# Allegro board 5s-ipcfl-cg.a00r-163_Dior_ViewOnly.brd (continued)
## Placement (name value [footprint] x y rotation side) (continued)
NOREF#46  -  []  13.39 44.26 90 top
NOREF#47  -  []  166 159.41 0 top
NOREF#48  -  []  144.75 74.89 0 top
NOREF#49  -  []  155.12 72.43 0 top
NOREF#50  -  [unnamed#2]  162 -0.25 0 top
NOREF#51  -  []  84.83 83.9 0 top
NOREF#52  -  []  118.2 39.88 0 top
NOREF#53  -  []  45.1 152.23 90 top
NOREF#54  -  []  2.67 129.75 0 top
NOREF#55  -  []  130.87 39.99 0 top
NOREF#56  -  []  106.22 27.09 0 top
NOREF#57  -  []  63.17 20.57 0 top
NOREF#58  -  []  98.11 26.85 0 top
NOREF#59  -  []  86 151.54 90 top
NOREF#60  -  []  129.26 29.83 0 top
NOREF#61  -  []  64.82 19.9 90 top
NOREF#62  -  []  166.02 159.91 0 top
NOREF#63  -  []  137.85 30.01 0 top
NOREF#64  -  []  50.62 160.7 0 top
NOREF#65  -  []  -76.75 -39.55 0 top
NOREF#66  -  []  21.55 47.33 90 top
NOREF#67  -  [unnamed#3]  65.15 137.2 0 top
NOREF#68  -  []  65.18 78.85 0 top
NOREF#69  -  []  137.11 29.24 0 top
NOREF#70  -  []  58.37 67.54 90 top
NOREF#71  -  [unnamed#3]  129.44 12.66 180 bottom
NOREF#72  -  []  9.19 176.57 180 bottom
NOREF#73  -  [unnamed#3]  12.42 157.57 180 bottom
NOREF#74  -  [unnamed#3]  -12.74 171.02 180 bottom
NOREF#75  -  [unnamed#3]  67.16 136.06 180 bottom
NOREF#76  -  [unnamed#3]  3.31 19.25 180 bottom
O2C1  2200PF/50V  [MX_C0402_SMALL_T01]  18.15 90.72 180 bottom
O2C2  100PF/50V  [MX_C0402_SMALL_T01]  154.15 14.42 90 top
O2C6  100PF/50V  [MX_C0402_SMALL_T01]  24.35 83.64 90 top
O2C7  2200PF/50V  [MX_C0402_SMALL_T01]  19.76 90.87 180 bottom
O2C8  100PF/50V  [MX_C0402_SMALL_T01]  16.08 88.74 90 top
O2CB1  0.1UF/16V  [MX_C0402_SMALL_T01]  26.77 98.9 0 bottom
O2CB2  0.1UF/16V  [MX_C0402_SMALL_T01]  12.81 90.91 180 bottom
O2CB3  0.1UF/16V  [MX_C0402_SMALL_T01]  10.65 91.1 180 bottom
O2CB4  0.1UF/16V  [MX_C0402_SMALL_T01]  5.7 94.37 180 bottom
O2CB5  0.1UF/16V  [MX_C0402_SMALL_T01]  18.82 111.81 90 bottom
O2CB6  0.1UF/16V  [MX_C0402_SMALL_T01]  16.53 90.77 0 bottom
O2CB7  1UF/6.3V  [TX_C0201_T009_H14]  24.03 99.58 90 top
O2CB8  0.1UF/16V  [MX_C0402_SMALL_T01]  26.74 105.58 0 bottom
O2CB10  0.1UF/16V  [MX_C0402_SMALL_T01]  26.67 95.93 0 bottom
O2CB11  0.1UF/16V  [MX_C0402_SMALL_T01]  26.71 97.07 180 bottom
O2CB15  0.1UF/16V  [MX_C0402_SMALL_T01]  21.91 90.25 0 bottom
O2CB16  0.1UF/16V  [MX_C0402_SMALL_T01]  5.93 99.06 180 bottom
O2CB17  0.1UF/16V  [MX_C0402_SMALL_T01]  11.23 110.91 90 bottom
O2CB19  0.1UF/16V  [MX_C0402_SMALL_T01]  16.08 90.49 270 top
O2CB20  0.1UF/16V  [MX_C0402_SMALL_T01]  27.51 91.81 0 bottom
O2CB21  0.1UF/16V  [MX_C0402_SMALL_T01]  27.23 112.51 180 bottom
O2Q2  MBT3904DW1T1G  [MX_SOT363_PHILIPS]  9.89 116.71 90 bottom
O2Q3  MBT3904DW1T1G  [MX_SOT363_PHILIPS]  14.18 116.46 270 bottom
O2Q4  MBT3904DW1T1G  [MX_SOT363_PHILIPS]  38.06 110.81 270 bottom
O2Q5  MBT3904DW1T1G  [MX_SOT363_PHILIPS]  44.4 135.6 90 bottom
O2R1  43.2  [MX_R0402_SMALL_T01]  29.82 94.35 270 bottom
O2R9  8.2K  [MX_R0402_SMALL_T01]  11.43 104.3 180 top
O2R10  330K  [MX_R0402_SMALL_T01]  21.74 70.59 0 bottom
O2R12  30KOHM  [MX_R0402_SMALL_T01]  10.45 114.93 180 bottom
O2R13  10.7KOHM  [MX_R0402_SMALL_T01]  14.21 119.33 0 bottom
O2R14  10KOhm  [MX_R0402_SMALL_T01]  13.62 120.75 90 bottom
O2R15  30KOHM  [MX_R0402_SMALL_T01]  14.45 118.34 180 bottom
O2R22  2.74K  [MX_R0402_SMALL_T01]  16.81 92.7 270 top
O2R24  8.2KOHM  [MX_R0402_SMALL_T01]  17.73 92.7 270 top
O2R25  8.2K  [MX_R0402_SMALL_T01]  21.74 71.52 180 bottom
OR3  1K  [MX_R0402_SMALL_T01]  26.08 93.51 180 bottom
OR22  10K  [MX_R0402_SMALL_T01]  18.53 113.45 90 bottom
OR29  10K  [MX_R0402_SMALL_T01]  23.03 113.51 270 bottom
OR34  1K  [MX_R0402_SMALL_T01]  21.94 113.5 270 bottom
OR37  10K  [MX_R0402_SMALL_T01]  13.71 113.36 90 bottom
OR59  10K  [MX_R0402_SMALL_T01]  13.79 98.75 180 top
OR68  10K  [MX_R0402_SMALL_T01]  17.17 114 0 bottom
OR69  10K  [MX_R0402_SMALL_T01]  17.17 113.08 0 bottom
OR70  10K  [MX_R0402_SMALL_T01]  17.17 112.17 0 bottom
OR71  10K  [MX_R0402_SMALL_T01]  17.17 111.25 0 bottom
OR72  10K  [MX_R0402_SMALL_T01]  11.44 103.38 180 top
OR73  10K  [MX_R0402_SMALL_T01]  8.14 110.2 180 bottom
OR74  10K  [MX_R0402_SMALL_T01]  8.14 111.14 180 bottom
OR75  10K  [MX_R0402_SMALL_T01]  8.14 112.05 180 bottom
OR76  10K  [MX_R0402_SMALL_T01]  6.75 117.01 180 bottom
OR77  10K  [MX_R0402_SMALL_T01]  10.45 114.02 0 bottom
OR78  10K  [MX_R0402_SMALL_T01]  10.5 113.1 0 bottom
OR79  10K  [MX_R0402_SMALL_T01]  10.45 112.18 0 bottom
OR109  10K  [MX_R0402_SMALL_T01]  9.37 103.58 180 top
OR111  10K  [MX_R0402_SMALL_T01]  9.37 104.53 180 top
OR112  10K  [MX_R0402_SMALL_T01]  9.37 105.48 180 top
OR118  10K  [MX_R0402_SMALL_T01]  12.88 93.31 180 top
OR119  10K  [MX_R0402_SMALL_T01]  9.37 102.66 180 top
OR120  10K  [MX_R0402_SMALL_T01]  6.05 104.54 180 bottom
OR122  10K  [MX_R0402_SMALL_T01]  6.04 106.37 180 bottom
OR123  10K  [MX_R0402_SMALL_T01]  5.71 107.29 180 bottom
OR124  10K  [MX_R0402_SMALL_T01]  8.02 91.1 0 bottom
OR125  10K  [MX_R0402_SMALL_T01]  6.41 91.1 0 bottom
OR126  10K  [MX_R0402_SMALL_T01]  8.48 93.59 45 top
OR127  10K  [MX_R0402_SMALL_T01]  6.58 92.19 90 top
OR128  10K  [MX_R0402_SMALL_T01]  7.75 103.22 0 top
OR129  10K  [MX_R0402_SMALL_T01]  5.74 101.96 0 top
OR130  10K  [MX_R0402_SMALL_T01]  5.74 101.02 0 top
OR132  10K  [MX_R0402_SMALL_T01]  11.75 112.85 90 bottom
OR133  10K  [MX_R0402_SMALL_T01]  12.69 112.85 90 bottom
OR134  10K  [MX_R0402_SMALL_T01]  14.65 113.36 90 bottom
OR135  10K  [MX_R0402_SMALL_T01]  14.4 110.78 90 bottom
OR136  10K  [MX_R0402_SMALL_T01]  15.6 113.37 90 bottom
OR137  10K  [MX_R0402_SMALL_T01]  15.33 111.31 90 bottom
OR141  10K  [MX_R0402_SMALL_T01]  10.76 96.19 180 top
OR142  10K  [MX_R0402_SMALL_T01]  5.7 96.24 0 bottom
OR143  10K  [MX_R0402_SMALL_T01]  10.75 98.23 0 top
OR144  0Ohm  [MX_R0402_SHORT_SMALL_T01]  9.37 101.74 180 top
OR146  10K  [MX_R0402_SMALL_T01]  18.02 100.78 180 top
OR147  10K  [MX_R0402_SMALL_T01]  18.02 99.84 180 top
OR148  10K  [MX_R0402_SMALL_T01]  16.05 95.06 180 top
OR149  10K  [MX_R0402_SMALL_T01]  16.05 96.05 180 top
OR150  10K  [MX_R0402_SMALL_T01]  16.05 96.97 0 top
OR151  10K  [MX_R0402_SMALL_T01]  16.05 98.01 0 top
OR152  10K  [MX_R0402_SMALL_T01]  36.75 109.03 0 bottom
OR153  10K  [MX_R0402_SMALL_T01]  11.25 92.75 0 top
OR154  1K  [MX_R0402_SMALL_T01]  21.87 74.74 0 bottom
P6  WAFER_HD_1X4P  [MX_WAFER_HD_4P_79_H_F71_LF5]  166.5 59.3 270 top
P12  FPC_CON_12P  [MX_FPC_12P_39_4HOLD_AC]  4.22 123.85 270 top
P70  WAFER_HD_1X4P  [MX_WAF_HD_1X4P_79_H_F71_LF5]  166.69 70.3 270 top
P110  SATA_CON_22P  [MX_SATA_22P_6HD_RA_LOTE_LF5]  42.08 124.48 0 top
P305  TACT_SWITCH_4P  [MX_SW_4P_2HOLD_RA_DIPT]  68.8 7.05 0 top
P466  HEADER_2X7P  [MX_HD_2X7P_100_XINYA_NOMASK]  43.88 50.64 0 bottom
PC1  0.22UF/25V  [TX_C0603]  163.8 153.53 270 top
PC4  1UF/50V  [MX_C0805_SMALL_T02]  164.84 150.43 270 bottom
PC5  0.1UF/25V  [MX_C0402_SMALL_T01]  166.19 140.5 270 top
PC17  1UF/16V  [MX_C0603_SMALL_T01]  47.39 136.72 180 top
PC19  10UF/25V  [MX_C0805_SMALL_T02]  29.5 116.91 270 top
PC20  10UF/25V  [MX_C0805_SMALL_T02]  27.73 116.91 270 top
PC21  0.01UF/50V  [MX_C0402_SMALL_T01]  50.52 138.9 90 top
PC22  2.2UF/6.3V  [MX_C0603_SMALL_T01]  59.99 139.46 0 bottom
PC23  0.1UF/25V  [MX_C0603_SMALL_T01]  57 133.52 90 bottom
PC24  0.01UF/50V  [MX_C0402_SMALL_T01]  51.46 138.9 90 top
PC25  10UF/6.3V  [MX_C0603_SMALL_T01]  81.38 110.48 90 top
PC26  1000PF/50V  [MX_C0402_SMALL_T01]  34.15 117.98 270 top
PC27  22UF/6.3V  [MX_C0603_SMALL_T02]  45.72 119.75 90 top
PC28  39PF/50V  [MX_C0402_SMALL_T01]  81.43 103.8 0 top
PC29  680PF/50V  [MX_C0402_SMALL_T01]  30.33 115.91 180 bottom
PC30  0.047UF/16V  [MX_C0402_SMALL_T01]  81.41 106.11 90 top
PC31  22UF/6.3V  [MX_C0603_SMALL_T02]  81.38 97.88 270 top
PC32  1000PF/50V  [MX_C0402_SMALL_T01]  28.55 115.51 270 bottom
PC33  22UF/6.3V  [MX_C0603_SMALL_T02]  73.79 106.03 180 top
PC34  1000PF/50V  [MX_C0402_SMALL_T01]  32.59 113.72 180 top
PC35  560PF/50V  [MX_C0402_SMALL_T01]  48.94 132.37 90 top
PC36  0.1UF/25V  [MX_C0603_SMALL_T01]  47.47 139.66 90 top
PC37  56PF/50V  [MX_C0402_SMALL_T01]  46.94 134.97 0 top
PC38  22UF/6.3V  [MX_C0603_SMALL_T02]  114.66 113.02 0 top
PC39  22UF/6.3V  [MX_C0603_SMALL_T02]  112.11 111.27 0 bottom
PC40  22UF/6.3V  [MX_C0603_SMALL_T02]  112.11 112.59 0 bottom
PC41  22UF/6.3V  [MX_C0603_SMALL_T02]  112.98 115.31 0 bottom
PC42  22UF/6.3V  [MX_C0603_SMALL_T02]  112.11 109.93 0 bottom
PC43  22UF/6.3V  [MX_C0603_SMALL_T02]  112.95 113.91 0 bottom
PC44  22UF/6.3V  [MX_C0603_SMALL_T02]  114.66 111.62 0 top
PC45  10UF/25V  [MX_C0805_SMALL_T02]  126.74 19.6 180 bottom
PC46  10UF/25V  [MX_C0805_SMALL_T02]  126.74 17.72 180 bottom
PC47  10UF/25V  [MX_C0805_SMALL_T02]  126.74 19.5 180 top
PC48  10UF/25V  [MX_C0805_SMALL_T02]  127.61 15.86 180 bottom
PC49  0.1UF/25V  [MX_C0402_SMALL_T01]  142.34 10.43 0 top
PC50  0.1UF/25V  [MX_C0603_SMALL_T01]  112.81 31.77 90 bottom
PC51  0.1UF/25V  [MX_C0603_SMALL_T01]  107.17 23.75 90 bottom
PC52  330PF/50V  [MX_C0402_SMALL_T01]  132.14 14.93 270 top
PC53  1UF/16V  [MX_C0603_SMALL_T01]  112.1 29.26 90 bottom
PC54  1UF/16V  [MX_C0603_SMALL_T01]  104.12 29.46 90 bottom
PC55  0.1UF/25V  [MX_C0603_SMALL_T01]  99.08 19.19 90 top
PC56  10UF/6.3V  [MX_C0603_SMALL_T01]  100.35 19.19 90 top
PC57  330PF/50V  [MX_C0402_SMALL_T01]  130.66 8.73 180 top
PC58  10PF/50V  [MX_C0402_SMALL_T01]  116.84 18.96 90 top
PC59  1000PF/50V  [MX_C0402_SMALL_T01]  127.53 9.5 0 bottom
PC60  0.1UF/16V  [MX_C0402_SMALL_T01]  112.25 27.17 270 bottom
PC61  56PF/50V  [MX_C0402_SMALL_T01]  104.76 27.47 90 bottom
PC62  0.1UF/16V  [MX_C0402_SMALL_T01]  102.35 26.97 180 bottom
PC63  10UF/25V  [MX_C0805_SMALL_T02]  83.64 28.06 270 bottom
PC64  10UF/25V  [MX_C0805_SMALL_T02]  85.47 28.06 270 bottom
PC65  0.1UF/25V  [MX_C0603_SMALL_T01]  108.57 33.37 270 bottom
PC66  330PF/50V  [MX_C0402_SMALL_T01]  86.13 32.48 90 bottom
PC67  0.1UF/16V  [MX_C0402_SMALL_T01]  103.17 24.63 90 bottom
PC68  330PF/50V  [MX_C0402_SMALL_T01]  86.11 35 90 bottom
PC69  0.1UF/25V  [MX_C0603_SMALL_T01]  63.73 38.9 180 top
PC70  10UF/6.3V  [MX_C0603_SMALL_T01]  63.73 37.68 180 top
PC71  10PF/50V  [MX_C0402_SMALL_T01]  74.7 40.88 0 top
PC72  1000PF/50V  [MX_C0402_SMALL_T01]  84.33 39.66 0 bottom
PC73  0.1UF/16V  [MX_C0402_SMALL_T01]  106.16 33.4 180 bottom
PC74  56PF/50V  [MX_C0402_SMALL_T01]  104.8 31.49 270 bottom
PC75  0.1UF/16V  [MX_C0402_SMALL_T01]  102.6 32 180 bottom
PC76  1UF/6.3V  [TX_C0201_T009_H14]  68.45 43.27 0 bottom
PC78  0.1UF/16V  [MX_C0402_SMALL_T01]  69.95 43.32 270 bottom
PC79  1UF/16V  [MX_C0603_SMALL_T01]  67.38 48.03 0 bottom
PC81  0.1UF/16V  [MX_C0402_SMALL_T01]  69.34 47.87 180 bottom
PC92  10UF/25V  [MX_C0805_SMALL_T02]  76.82 69.85 90 top
PC93  10UF/25V  [MX_C0805_SMALL_T02]  78.6 69.85 90 top
PC94  0.1UF/25V  [MX_C0402_SMALL_T01]  80.48 64.52 180 top
PC95  0.1UF/16V  [MX_C0402_SMALL_T01]  72.63 65.73 270 top
PC96  0.1UF/25V  [MX_C0603_SMALL_T01]  68.92 71.02 0 top
PC97  4.7UF/6.3V  [MX_C0603_SMALL_T01]  69.25 67.66 180 top
PC99  680PF/50V  [MX_C0402_SMALL_T01]  73.01 72.01 0 top
PC102  1000PF/50V  [MX_C0402_SMALL_T01]  74.61 70.69 0 bottom
PC104  56PF/50V  [MX_C0402_SMALL_T01]  74.66 65.53 90 top
PC105  0.1UF/16V  [MX_C0402_SMALL_T01]  76.9 65.33 0 top
PC106  0.1UF/16V  [MX_C0402_SMALL_T01]  73.28 102.48 0 bottom
PC107  22UF/6.3V  [MX_C0603_SMALL_T02]  70.41 99.56 180 bottom
PC108  1UF/25V  [MX_C0603_SMALL_T01]  68.58 102.96 90 bottom
PC109  0.1UF/16V  [MX_C0402_SMALL_T01]  102.59 42.28 270 bottom
PC110  1UF/6.3V  [TX_C0201_T009_H14]  101.62 39.13 0 bottom
PC111  10UF/6.3V  [MX_C0603_SMALL_T01]  101.46 40.76 90 bottom
PC112  10UF/6.3V  [MX_C0603_SMALL_T01]  90.41 39.37 270 bottom
PC113  10UF/6.3V  [MX_C0603_SMALL_T01]  91.68 39.37 270 bottom
PC114  33PF/50V  [MX_C0402_SMALL_T01]  91.8 41.4 90 bottom
PC115  1UF/6.3V  [TX_C0201_T009_H14]  34.8 25.97 90 bottom
PC116  1UF/6.3V  [TX_C0201_T009_H14]  28.75 25.36 90 bottom
PC117  1UF/16V  [MX_C0603_SMALL_T01]  142.41 29.46 0 bottom
PC118  0.1UF/25V  [MX_C0603_SMALL_T01]  140.75 23.31 270 bottom
PC119  0.1UF/25V  [MX_C0402_SMALL_T01]  130.25 20.51 90 bottom
PC120  1000PF/50V  [MX_C0402_SMALL_T01]  136.79 32.41 90 bottom
PC121  10UF/25V  [MX_C0805_SMALL_T02]  136.09 9.59 270 top
PC122  10UF/25V  [MX_C0805_SMALL_T02]  134.31 9.59 270 top
PC123  330PF/50V  [MX_C0402_SMALL_T01]  136.24 12.44 0 bottom
PC124  0.1UF/16V  [MX_C0402_SMALL_T01]  138.03 32 90 bottom
PC125  680PF/50V  [MX_C0402_SMALL_T01]  137.64 14.47 90 bottom
PC126  10UF/6.3V  [MX_C0603_SMALL_T01]  147.13 29.71 180 bottom
PC127  1000PF/50V  [MX_C0402_SMALL_T01]  139.37 17.87 180 bottom
PC128  1UF/6.3V  [TX_C0201_T009_H14]  139.99 32 90 bottom
PC129  330PF/50V  [MX_C0402_SMALL_T01]  135.99 17.06 0 top
PC130  56PF/50V  [MX_C0402_SMALL_T01]  134.58 31.95 0 bottom
PC134  10UF/6.3V  [MX_C0603_SMALL_T01]  133.21 25.02 270 bottom
PC135  10UF/6.3V  [MX_C0603_SMALL_T01]  134.22 27.43 90 bottom
PC760  1UF/6.3V  [MX_C0402_SMALL_T01]  34.52 101.11 270 bottom
PC761  1UF/6.3V  [MX_C0402_SMALL_T01]  35.15 104.74 0 bottom
PC762  0.1UF/16V  [MX_C0402_SMALL_T01]  29.31 106.67 270 bottom
PC802  22UF/6.3V  [MX_C0805_SMALL_T02]  72.52 88.64 0 top
PC803  22UF/6.3V  [MX_C0805_SMALL_T02]  67.9 82.85 180 top
PC804  22UF/6.3V  [MX_C0805_SMALL_T02]  70.99 93.13 270 bottom
PC808  0.01UF/50V  [MX_C0402_SMALL_T01]  70.65 65.73 270 top
PC812  22UF/6.3V  [MX_C0805_SMALL_T02]  72.45 86.74 0 top
PC813  22UF/6.3V  [MX_C0603_SMALL_T02]  72.09 91.97 0 top
PC814  22UF/6.3V  [MX_C0603_SMALL_T02]  72.11 90.54 0 top
PC815  22UF/6.3V  [MX_C0805_SMALL_T02]  72.44 82.92 0 top
PC816  22UF/6.3V  [MX_C0805_SMALL_T02]  72.44 84.83 0 top
PC998  10UF/25V  [MX_C0805_SMALL_T02]  166.39 81.02 0 top
PC999  10UF/25V  [MX_C0805_SMALL_T02]  160.02 145.02 270 top
PC6301  0.1UF/25V  [MX_C0402_SMALL_T01]  36.07 148.48 0 bottom
PC6302  1UF/16V  [MX_C0603_SMALL_T02_H37]  38 140.68 270 bottom
PC6303  10UF/16V  [MX_C0805_SMALL_T02]  39.57 140.4 270 bottom
PC6304  0.1UF/16V  [MX_C0402_SMALL_T01]  35.86 140.81 270 bottom
PC6305  1UF/50V  [MX_C0805_SMALL_T02]  41.83 140.91 180 bottom
PC6306  0.01UF/50V  [MX_C0402_SMALL_T01]  42.44 144.64 90 bottom
PC6307  0.1UF/16V  [MX_C0402_SMALL_T01]  31.24 139.82 90 bottom
PC6308  0.01UF/50V  [MX_C0402_SMALL_T01]  36.8 140.81 270 bottom
PC7310  0.1UF/25V  [MX_C0402_SMALL_T01]  77.32 67.66 270 top
PC7601  10UF/6.3V  [MX_C0603_SMALL_T01]  63.1 61.76 180 bottom
PC7602  10UF/6.3V  [MX_C0603_SMALL_T01]  63.1 60.56 180 bottom
PC7603  33PF/50V  [MX_C0402_SMALL_T01]  65.01 60.65 0 bottom
PC7604  10UF/6.3V  [MX_C0603_SMALL_T01]  62.94 51.4 180 bottom
PC7605  1UF/16V  [MX_C0603_SMALL_T01]  60.73 53.08 90 bottom
PC7606  0.1UF/16V  [MX_C0402_SMALL_T01]  67.94 53.23 0 bottom
PC7607  0.1UF/16V  [MX_C0402_SMALL_T01]  29.54 23.84 270 bottom
PC7801  1UF/6.3V  [TX_C0201_T009_H14]  34.8 24.75 270 bottom
PC7802  1UF/6.3V  [TX_C0201_T009_H14]  29.49 25.36 90 bottom
PC7899  0.1UF/16V  [MX_C0402_SMALL_T01]  35.41 24.37 270 top
PC8498  0.1UF/16V  [MX_C0402_SMALL_T01]  45.19 43.65 0 bottom
PC8499  0.1UF/16V  [MX_C0402_SMALL_T01]  43.74 42.41 270 bottom
PC9001  0.1UF/25V  [TX_C0402]  127.15 152.09 270 bottom
PC9002  0.1UF/25V  [MX_C0402_SMALL_T01]  111.25 152.16 270 top
PC9003  0.1UF/25V  [TX_C0402]  98.83 152.24 270 top
PC9416  0.1UF/16V  [MX_C0402_SMALL_T01]  98.91 8.14 270 top
PC89001  1UF/6.3V  [MX_C0402_SMALL_T01]  86.54 170.47 270 top
PC89002  0.1UF/16V  [MX_C0402_SMALL_T01]  89.08 158.51 0 top
PC89003  2200PF/50V  [MX_C0402_SMALL_T01]  84.56 163.82 180 bottom
PC89004  0.01UF/50V  [MX_C0402_SMALL_T01]  92.96 168.95 90 bottom
PC89005  1000PF/50V  [MX_C0402_SMALL_T01]  89.13 156.96 270 bottom
PC89006  4.7UF/6.3V  [MX_C0603_SMALL_T01]  98.86 168.24 90 top
PC89007  0.047UF/16V  [MX_C0402_SMALL_T01]  86.56 168.39 90 bottom
PC89008  0.1UF/16V  [MX_C0402_SMALL_T01]  88.29 157.6 0 top
PC89009  0.1UF/16V  [MX_C0402_SMALL_T01]  90.75 168.7 180 bottom
PC89010  0.1UF/16V  [MX_C0402_SMALL_T01]  87.35 159.12 270 bottom
PC89011  0.1UF/16V  [MX_C0402_SMALL_T01]  84.94 158.61 180 bottom
PC89012  470PF/50V  [MX_C0402_SMALL_T01]  84.71 166.87 0 bottom
PC89013  47PF/50V  [MX_C0402_SMALL_T01]  85.83 164.33 90 bottom
PC89014  0.1UF/16V  [MX_C0402_SMALL_T01]  86.1 159.45 180 top
PC89015  0.1UF/16V  [MX_C0402_SMALL_T01]  86.51 160.77 270 bottom
PC89016  1000PF/50V  [MX_C0402_SMALL_T01]  85.52 165.95 90 top
PC89017  0.1UF/16V  [MX_C0402_SMALL_T01]  86.82 165.37 270 top
PC89018  560PF/50V  [MX_C0402_SMALL_T01]  85.95 161.91 270 top
PC89019  2200PF/50V  [MX_C0402_SMALL_T01]  85.95 167.25 0 top
PC89020  1000PF/50V  [MX_C0402_SMALL_T01]  84.94 161.91 270 top
PC89021  470PF/50V  [MX_C0402_SMALL_T01]  89.89 165.8 0 top
PC89022  1000PF/50V  [MX_C0402_SMALL_T01]  86.51 162.55 270 bottom
PC89023  470PF/50V  [MX_C0402_SMALL_T01]  98.02 165.22 0 top
PC89024  2200PF/50V  [MX_C0402_SMALL_T01]  100.3 163.44 0 bottom
PC89025  47PF/50V  [MX_C0402_SMALL_T01]  96.8 164.38 90 bottom
PC89026  0.1UF/16V  [MX_C0402_SMALL_T01]  96.09 159.91 270 bottom
PC89027  1000PF/50V  [MX_C0402_SMALL_T01]  98.86 166.49 90 bottom
PC89028  0.1UF/16V  [MX_C0402_SMALL_T01]  97.07 165.85 0 bottom
PC89029  0.1UF/16V  [MX_C0402_SMALL_T01]  98.7 161.91 0 bottom
PC89030  0.1UF/16V  [MX_C0402_SMALL_T01]  97.26 161.53 270 bottom
PC89031  2200PF/50V  [MX_C0402_SMALL_T01]  97.23 166.92 180 bottom
PC89032  120PF/50V  [MX_C0402_SMALL_T01]  94.13 162.35 90 top
PC89033  470PF/50V  [MX_C0402_SMALL_T01]  95.48 165.47 270 top
PC89034  1000PF/50V  [MX_C0402_SMALL_T01]  93.22 162.35 90 top
PC89035  1000PF/50V  [MX_C0402_SMALL_T01]  96.75 161.1 180 top
PC89036  0.1UF/16V  [MX_C0402_SMALL_T01]  87.1 156.96 270 bottom
PC89037  0.1UF/16V  [MX_C0402_SMALL_T01]  95.25 168.9 90 bottom
PC90001  10uF/25V  [TX_C0805_T02_H57]  122.07 151.65 270 bottom
PC90002  4.7UF/25V  [MX_C0805_SMALL_T02_H55]  125.58 150.99 270 bottom
PC90003  10UF/25V  [MX_C0805_SMALL_T02]  130.94 151.75 270 bottom
PC90005  0.1UF/25V  [MX_C0603_SMALL_T01]  119.33 147.11 270 bottom
PC90006  1000PF/50V  [MX_C0402_SMALL_T01]  127.35 155.44 180 top
PC90007  1UF/16V  [TX_C0603_T015_H37]  116.58 150.99 0 bottom
PC90008  680PF/50V  [MX_C0402_SMALL_T01]  122.91 147.16 90 top
PC90009  1000PF/50V  [MX_C0402_SMALL_T01]  129.64 148.45 90 bottom
PC90010  680PF/50V  [MX_C0402_SMALL_T01]  130.17 150.87 90 top
PC90012  10UF/25V  [MX_C0805_SMALL_T02]  103.71 152.92 180 top
PC90013  10uF/25V  [TX_C0805_T02_H57]  103.71 154.75 180 top
PC90016  0.1UF/25V  [MX_C0603_SMALL_T01]  104.01 148.71 270 bottom
PC90017  1000PF/50V  [MX_C0402_SMALL_T01]  109.4 155.56 180 top
PC90018  680PF/50V  [MX_C0402_SMALL_T01]  105.05 147.72 90 top
PC90019  1UF/16V  [TX_C0603_T015_H37]  100.39 152.39 90 bottom
PC90020  1000PF/50V  [MX_C0402_SMALL_T01]  105.46 148.4 90 bottom
PC90021  680PF/50V  [MX_C0402_SMALL_T01]  111.45 150 90 top
PC90100  0.1UF/25V  [TX_C0402]  162.33 150.99 0 top
PC93001  10UF/25V  [MX_C0805_SMALL_T02]  131.82 147.74 270 top
PC93002  10uF/25V  [TX_C0805_T02_H57]  133.6 147.74 270 top
PC93003  10UF/25V  [MX_C0805_SMALL_T02]  134.4 13.73 90 top
PC93005  0.1UF/25V  [MX_C0603_SMALL_T01]  165.61 125.36 90 top
PC93006  1000PF/50V  [MX_C0402_SMALL_T01]  137.87 149.14 270 bottom
PC93007  1UF/25V  [MX_C0603_SMALL_T01]  162.45 121.9 180 top
PC93008  680PF/50V  [MX_C0402_SMALL_T01]  134.69 146.52 180 bottom
PC93009  1000PF/50V  [MX_C0402_SMALL_T01]  131.98 147.11 270 bottom
PC93010  1000PF/50V  [MX_C0402_SMALL_T01]  136.98 142.56 180 top
PC93012  10UF/25V  [MX_C0805_SMALL_T02]  165.45 110.48 180 bottom
PC93013  10UF/25V  [MX_C0805_SMALL_T02]  165.45 108.7 180 bottom
PC93016  0.1UF/25V  [MX_C0603_SMALL_T01]  157.48 119.7 180 bottom
PC93017  1000PF/50V  [MX_C0402_SMALL_T01]  166.91 102.37 180 top
PC93018  1UF/16V  [TX_C0603_T015_H37]  158.94 125.39 0 bottom
PC93019  680PF/50V  [MX_C0402_SMALL_T01]  162.33 108.55 180 top
PC93020  1000PF/50V  [MX_C0402_SMALL_T01]  164.79 97.53 180 top
PC93021  1000PF/50V  [MX_C0402_SMALL_T01]  162.33 102.38 180 top
PC97001  22UF/6.3V  [MX_C0603_SMALL_T02]  126.15 117.53 180 top
PC97002  22UF/6.3V  [MX_C0603_SMALL_T02]  123.1 117.53 0 top
PC97003  22UF/6.3V  [MX_C0603_SMALL_T02]  123.1 116.13 0 top
PC97004  22UF/6.3V  [MX_C0603_SMALL_T02]  118.15 114.9 0 top
PC97005  22UF/6.3V  [MX_C0603_SMALL_T02]  126.15 109.15 180 top
PC97006  22UF/6.3V  [MX_C0603_SMALL_T02]  126.15 111.94 180 top
PC97007  22UF/6.3V  [MX_C0603_SMALL_T02]  126.15 110.55 180 top
PC97008  22UF/6.3V  [MX_C0603_SMALL_T02]  123.1 114.74 0 top
PC97009  22UF/6.3V  [MX_C0603_SMALL_T02]  118.15 110.86 0 top
PC97010  22UF/6.3V  [MX_C0603_SMALL_T02]  123.61 106.48 180 top
PC97011  22UF/6.3V  [MX_C0603_SMALL_T02]  123.1 111.94 0 top
PC97012  22UF/6.3V  [MX_C0603_SMALL_T02]  123.1 110.55 0 top
PC97013  22UF/6.3V  [MX_C0603_SMALL_T02]  115.58 115.96 180 bottom
PC97014  22UF/6.3V  [MX_C0603_SMALL_T02]  123.1 113.34 0 top
PC97015  22UF/6.3V  [MX_C0603_SMALL_T02]  126.15 113.34 180 top
PC97016  22UF/6.3V  [MX_C0603_SMALL_T02]  126.15 114.74 180 top
PC97017  22UF/6.3V  [MX_C0603_SMALL_T02]  123.1 109.15 0 top
PC97018  22UF/6.3V  [MX_C0603_SMALL_T02]  118.15 113.58 0 top
PC97019  22UF/6.3V  [MX_C0603_SMALL_T02]  119.04 106.48 180 top
PC97020  22UF/6.3V  [MX_C0603_SMALL_T02]  118.14 112.23 0 top
PC97021  22UF/6.3V  [MX_C0603_SMALL_T02]  118.15 117.56 0 top
PC97022  22UF/6.3V  [MX_C0603_SMALL_T02]  118.15 116.22 0 top
PC97023  22UF/6.3V  [MX_C0603_SMALL_T02]  126.15 116.13 180 top
PC97024  22UF/6.3V  [MX_C0603_SMALL_T02]  132.68 109.4 270 top
PC97025  22UF/6.3V  [MX_C0603_SMALL_T02]  129.88 114.48 90 top
PC97026  22UF/6.3V  [MX_C0603_SMALL_T02]  128.49 114.48 90 top
PC97027  22UF/6.3V  [MX_C0603_SMALL_T02]  128.49 112.2 270 top
PC97028  22UF/6.3V  [MX_C0603_SMALL_T02]  132.68 114.48 90 top
PC97029  22UF/6.3V  [MX_C0603_SMALL_T02]  128.49 109.4 270 top
PC97030  22UF/6.3V  [MX_C0603_SMALL_T02]  129.88 109.4 270 top
PC97031  22UF/6.3V  [MX_C0603_SMALL_T02]  131.28 114.48 90 top
PC97032  22UF/6.3V  [MX_C0603_SMALL_T02]  131.28 112.2 270 top
PC97033  22UF/6.3V  [MX_C0603_SMALL_T02]  132.68 112.2 270 top
PC97034  22UF/6.3V  [MX_C0603_SMALL_T02]  135.37 112.14 270 bottom
PC97035  22UF/6.3V  [MX_C0603_SMALL_T02]  156.82 116.83 180 bottom
PC97036  22UF/6.3V  [MX_C0603_SMALL_T02]  129.88 112.2 270 top
PC97037  22UF/6.3V  [MX_C0603_SMALL_T02]  132.87 109.21 270 bottom
PC97038  22UF/6.3V  [MX_C0603_SMALL_T02]  157.33 107.94 90 bottom
PC97039  22UF/6.3V  [MX_C0603_SMALL_T02]  136.13 109.22 270 bottom
PC97040  22UF/6.3V  [MX_C0603_SMALL_T02]  134.73 109.22 270 bottom
PC97041  22UF/6.3V  [MX_C0603_SMALL_T02]  132.68 117.1 270 top
PC97042  22UF/6.3V  [MX_C0603_SMALL_T02]  131.28 117.1 270 top
PC97043  22UF/6.3V  [MX_C0603_SMALL_T02]  131.28 109.4 270 top
PC941483  0.1UF/16V  [MX_C0402_SMALL_T01]  133.84 35.18 90 bottom
PC941484  10UF/6.3V  [MX_C0603_SMALL_T01]  137.13 23.94 270 bottom
PC941485  1UF/6.3V  [TX_C0201_T009_H14]  134.42 25.01 270 bottom
PC941488  0.033U/16V  [MX_C0402_SMALL_T01]  134.25 30.4 180 bottom
PC941489  22UF/6.3V  [MX_C0603_SMALL_T02]  129.88 117.1 270 top
PC941490  22UF/6.3V  [MX_C0603_SMALL_T02]  128.49 117.1 270 top
PC941491  22UF/6.3V  [MX_C0603_SMALL_T02]  115.2 114.17 180 bottom
PC941492  22UF/6.3V  [MX_C0603_SMALL_T02]  115.17 112.14 180 bottom
PC941493  22UF/6.3V  [MX_C0603_SMALL_T02]  116.7 109.72 270 bottom
PC941494  22UF/6.3V  [MX_C0603_SMALL_T02]  118.3 109.72 270 bottom
PC941496  0.1UF/25V  [MX_C0402_SMALL_T01]  156.08 162.73 180 top
PC941497  0.01UF/25V  [MX_C0402_SMALL_T01]  167.26 141.34 90 top
PC941502  0.1UF/16V  [MX_C0402_SMALL_T01]  33.37 145.46 270 bottom
PC941579  1000PF/50V  [MX_C0402_SMALL_T01]  70.69 46.09 0 bottom
PC941580  1000PF/50V  [MX_C0402_SMALL_T01]  70.69 45.15 0 bottom
PC941582  1UF/16V  [MX_C0402_SMALL_T01]  65.21 45.43 180 bottom
PC941584  2200PF/50V  [MX_C0402_SMALL_T01]  163.68 48.88 270 bottom
PC941585  2200PF/50V  [MX_C0402_SMALL_T01]  168.15 48.83 270 bottom
PC941586  680PF/50V  [MX_C0402_SMALL_T01]  92.58 147.28 180 top
PC941587  10UF/25V  [MX_C0805_SMALL_T02]  90.42 153.18 270 top
PC941588  0.1UF/25V  [MX_C0603_SMALL_T01]  87.2 145.99 180 top
PC941589  680PF/50V  [MX_C0402_SMALL_T01]  98.82 150.6 90 top
PC941590  1UF/16V  [TX_C0603_T015_H37]  90.07 141.34 90 top
PC941591  1000PF/50V  [MX_C0402_SMALL_T01]  96.82 156.05 180 bottom
PC941601  10UF/25V  [MX_C0805_SMALL_T02]  137.92 9.51 270 top
PC941602  1UF/6.3V  [TX_C0201_T009_H14]  42.44 41.06 180 bottom
PC941603  0.1UF/16V  [MX_C0402_SMALL_T01]  40.99 45.71 0 bottom
PC941604  1000PF/50V  [MX_C0402_SMALL_T01]  38.2 40.81 180 bottom
PC941605  1UF/16V  [MX_C0402_SMALL_T01]  45.53 42.35 0 bottom
PC941608  0.1UF/16V  [MX_C0402_SMALL_T01]  40.28 40.78 0 bottom
PC941609  1000PF/50V  [MX_C0402_SMALL_T01]  38.2 41.72 180 bottom
PC941610  1UF/16V  [MX_C0603_SMALL_T01]  43.64 45.82 180 bottom
PC941611  1UF/16V  [MX_C0603_SMALL_T01]  98.86 8.5 270 bottom
PC941612  0.1UF/16V  [MX_C0402_SMALL_T01]  95.6 13.66 90 bottom
PC941613  1000PF/50V  [MX_C0402_SMALL_T01]  94.21 8.88 270 top
PC941614  1UF/16V  [MX_C0402_SMALL_T01]  99.9 10.63 0 bottom
PC941617  0.1UF/16V  [MX_C0402_SMALL_T01]  94.56 8.17 270 bottom
PC941618  1UF/16V  [MX_C0603_SMALL_T01]  97.2 13.44 180 bottom
PC941619  1000PF/50V  [MX_C0402_SMALL_T01]  94.08 11.17 180 bottom
PC941620  0.1UF/50V  [MX_C0603_SMALL_T01]  155.85 161.46 180 top
PC941622  10UF/25V  [MX_C0805_SMALL_T02]  129.13 152.26 270 bottom
PC941623  1000PF/50V  [MX_C0402_SMALL_T01]  90.52 148.71 90 bottom
PC941626  10uF/25V  [TX_C0805_T02_H57]  92.2 153.18 270 top
PC941663  22UF/6.3V  [MX_C0603_SMALL_T02]  124.46 114.32 0 bottom
PC941664  22UF/6.3V  [MX_C0603_SMALL_T02]  124.46 115.84 0 bottom
PC941665  22UF/6.3V  [MX_C0603_SMALL_T02]  124.46 117.34 0 bottom
PC941666  0.01UF/25V  [MX_C0402_SMALL_T01]  167.26 139.66 270 top
PC941667  1UF/6.3V  [TX_C0201_T009_H14]  68.45 42.56 0 bottom
PC941669  1UF/6.3V  [TX_C0201_T009_H14]  101.62 38.39 0 bottom
PC941670  1UF/6.3V  [TX_C0201_T009_H14]  135.2 25.01 270 bottom
PC941671  1UF/6.3V  [TX_C0201_T009_H14]  44.5 41.14 90 bottom
PCE2  220UF/6.3V  [MX_CESMD_260X260_COLAY]  76.98 100.47 0 top
PCE3  560UF/2.5V  [MX_CESMD_260X260_SAN]  50.02 116.57 270 top
PCE4  560UF/2.5V  [MX_CESMD_260X260_SAN]  57.41 116.57 270 top
PCE5  220UF/6.3V  [MX_CESMD_260X260_COLAY]  106.78 16.75 180 top
PCE6  220UF/6.3V  [MX_CESMD_260X260_COLAY]  97.13 14.09 90 top
PCE7  220UF/6.3V  [MX_CESMD_260X260_COLAY]  66.17 33.39 90 top
PCE9  820UF/2.5V  [MX_CE_98_BD268_H374_37_LFH]  149.53 16.68 0 top
PCE31  27uF/25V  [MX_CESMD_209X209_CHEMICON]  145.49 154.02 0 top
PCE125  27uF/25V  [MX_CESMD_209X209_CHEMICON]  136.1 153.76 0 top
PCE690  220UF/6.3V  [MX_CESMD_260X260_COLAY]  67.38 44.08 0 top
PCE97027  560uF/2.5V  [MX_CE_79_BD217_H354HD31_LF5]  102.13 140.81 0 top
PCE97028  560uF/2.5V  [MX_CE_79_BD217_H354HD31_LF5]  140.18 140.68 270 top
PCE97030  560UF/2.5V  [MX_CESMD_260X260_SAN]  117.55 142.31 270 top
PCE97031  560uF/2.5V  [MX_CE_79_BD217_H354HD31_LF5]  133.68 140.71 0 top
PCE97032  330UF/2V  [MX_C7343D_H83]  131.21 115.37 90 bottom
PCE97033  560uF/2.5V  [MX_CE_79_BD217_H354HD31_LF5]  166.67 120.67 270 top
PCE97034  560uF/2.5V  [MX_CE_79_BD217_H354HD31_LF5]  162.66 141.16 270 top
PCE97035  560uF/2.5V  [MX_CE_79_BD217_H354HD31_LF5]  151.42 141.16 270 top
PCE97037  560uF/2.5V  [MX_CE_79_BD217_H354HD31_LF5]  145.85 140.81 270 top
PCE97038  560uF/2.5V  [MX_CE_79_BD217_H354HD31_LF5]  157.08 141.42 270 top
PD1  SS14  [MX_SMA]  167.23 147.94 270 top
PD4  BAT54CW  [MX_SOT323]  58.59 137.09 90 bottom
PD8  BAT54CW  [MX_SOT323]  32.22 147.72 0 bottom
PJP1  -  [SHORTPIN]  164.74 146.14 270 top
PJP2  -  [SHORTPIN]  162.71 146.14 270 top
PJP3  -  [SHORTPIN]  34.34 115.46 270 top
PJP4  -  [SHORTPIN]  57.43 116.09 90 top
PJP6  -  [SHORTPIN]  106.15 16.75 0 top
PJP7  -  [SHORTPIN]  66.19 34.05 270 top
PJP8  -  [SHORTPIN]  71.47 92.73 90 top
PJP9  -  [SHORTPIN]  150.78 17.62 90 top
PJP6801  -  [SHORTPIN]  77.54 100.9 0 top
PJP89001  -  [SHORTPIN]  139.52 132.37 180 bottom
PJP89002  -  [SHORTPIN]  139.55 131.1 180 bottom
PJP89003  -  [SHORTPIN]  144.58 123.51 180 bottom
PJP89004  -  [SHORTPIN]  144.58 124.65 180 bottom
PJP90001  -  [SHORTPIN]  126.97 144.26 270 top
PJP90002  -  [SHORTPIN]  126.85 140.96 90 top
PJP90003  -  [SHORTPIN]  108.81 144.26 270 top
PJP90004  -  [SHORTPIN]  108.81 141.09 90 top
PJP93001  -  [SHORTPIN]  144.04 147.21 0 top
PJP93002  -  [SHORTPIN]  147.34 147.21 180 top
PJP93003  -  [SHORTPIN]  165.28 111.55 90 top
PJP93004  -  [SHORTPIN]  165.28 114.88 270 top
PJP93005  -  [SHORTPIN]  95.55 141.14 90 top
PJP93006  -  [SHORTPIN]  95.55 144.16 270 top
PL1  70Ohm/100Mhz  [MX_L0603_SMALL_T02]  165.53 157.93 270 top
PL2  70Ohm/100Mhz  [MX_L0603_SMALL_T02]  162.79 157.93 270 top
PL3  70Ohm/100Mhz  [MX_L0603_SMALL_T02]  164.16 157.93 270 top
PL4  70Ohm/100Mhz  [MX_L0603_SMALL_T02]  166.88 157.93 270 top
PL7  70Ohm/100Mhz  [MX_L0603_SMALL_T02]  130 19.04 0 bottom
PL8  70Ohm/100Mhz  [MX_L0603_SMALL_T02]  130 17.72 0 bottom
PL9  70Ohm/100Mhz  [MX_L0603_SMALL_T02]  130 19.62 0 top
PL10  70Ohm/100Mhz  [MX_L0603_SMALL_T02]  130 16.98 0 top
PL11  3.3UH  [MX_INDUCTOR_2P_453X394_COLA]  119.64 12.65 180 top
PL12  3.3UH  [MX_INDUCTOR_2P_453X394_COLA]  76.91 35.09 180 top
PL13  1UH/11A  [MX_INDUCTOR_2P_287X260]  70.11 77.19 90 top
PL14  1UH/11A  [MX_INDUCTOR_2P_287X260]  142.16 15.66 90 top
PL90001  0.22uH  [MX_INDUCTOR_2P_274X260_COLA]  127.1 142.66 270 top
PL90002  0.22uH  [MX_INDUCTOR_2P_274X260_COLA]  108.74 142.66 270 top
PL90010  70Ohm/100Mhz  [MX_L0603_SMALL_T02]  157.8 144.92 0 top
PL90011  70Ohm/100Mhz  [MX_L0603_SMALL_T02]  157.8 146.24 0 top
PL90012  70Ohm/100Mhz  [MX_L0603_SMALL_T02]  157.8 147.56 0 top
PL90013  70Ohm/100Mhz  [MX_L0603_SMALL_T02]  157.8 148.88 0 top
PL93001  0.22uH  [MX_INDUCTOR_2P_274X260_COLA]  145.76 147.35 0 top
PL93002  0.22uH  [MX_INDUCTOR_2P_274X260_COLA]  165.25 113.15 90 top
PL93004  70Ohm/100Mhz  [MX_L0603_SMALL_T02]  139.93 10.2 0 top
PL93006  0.22uH  [MX_INDUCTOR_2P_274X260_COLA]  95.56 142.67 270 top
PL93010  1UH/11A/22A  [MX_INDUCTOR_2P_287X260]  40.26 116.19 0 top
PPID1  9D525X9D525  [LB1_LOGO_375X375]  7.75 1.48 180 bottom
PQ1  SI7121DN-T1-GE3  [MX_SI7900EDN_COLAY]  166.72 153.9 270 top
PQ5  SIRA18DP-T1-GE3  [MX_SI7850DP_COLAY]  77.87 107.79 0 top
PQ7  SIZ340DT-T1-GE3  [MX_DFN_8P_26_122X122_2PAD]  129.06 12.52 180 top
PQ8  SIZ340DT-T1-GE3  [MX_DFN_8P_26_122X122_2PAD]  83.97 32.86 180 bottom
PQ21  PMPB20EN  [MX_SC70_6_VISHAY_T01]  70.74 101.74 90 bottom
PQ22  RN47A4  [MX_SOT323_S5]  67.84 97.5 180 bottom
PQ23  SIZ340DT-T1-GE3  [MX_DFN_8P_26_122X122_2PAD]  136.9 13.58 0 top
PQ24  NX7002AK  [TX_SOT23_2D4_T01_H43]  139.83 37.38 0 bottom
PQ25  NX7002AK  [TX_SOT23_2D4_T01_H43]  136.27 37.38 0 bottom
PQ45  NX7002AK  [TX_SOT23_2D4_T01_H43]  17.22 121.3 180 top
PQ101  LMBT3904LT1G  [TX_SOT23_2D4_122X55_H44]  35.96 110.31 0 top
PQ102  LMBT3904LT1G  [TX_SOT23_2D4_122X55_H44]  30.45 109.78 270 top
PQ6301  NX7002AK  [TX_SOT23_2D4_T01_H43]  27.66 147.03 270 bottom
PQ9823  NX7002AK  [TX_SOT23_2D4_T01_H43]  11.07 126.89 90 bottom
PQ90001  FDPC5030SG  [TX_DFN_8P_201X240_2P_10V_CO]  126.13 150.64 180 top
PQ93001  FDMS3660S  [MX_DFN_8P_50_201X248_P_8V]  137.11 147.2 180 top
PQ93002  FDMS3660S  [MX_DFN_8P_50_201X248_P_8V]  165.59 105.48 90 top
PQ93008  FDPC5030SG  [TX_DFN_8P_201X240_2P_10V_CO]  108.18 151.35 180 top
PQ93010  NX7002AK  [TX_SOT23_2D4_T01_H43]  28.95 142.94 0 bottom
PQ93012  NX7002AK  [TX_SOT23_2D4_T01_H43]  49.76 143.32 270 top
PQ93018  FDPC5030SG  [TX_DFN_8P_201X240_2P_10V_CO]  95.73 151.35 180 top
PQ93028  NX7002AK  [TX_SOT23_2D4_T01_H43]  27.05 77.99 270 top
PQ93030  NX7002AK  [TX_SOT23_2D4_T01_H43]  27.55 110.35 270 bottom
PQ93031  NX7002AK  [TX_SOT23_2D4_T01_H43]  31.33 110.33 0 bottom
PQ93040  SIZ340DT-T1-GE3  [MX_DFN_8P_26_122X122_2PAD]  32.04 117.13 180 top
PR1  10mOHM  [MX_R1508]  163.73 148.3 180 top
PR2  100 Ohm  [MX_R0603_SMALL_T01]  164.57 153.86 270 bottom
PR3  100 Ohm  [MX_R0603_SMALL_T01]  165.84 153.86 270 bottom
PR4  100 Ohm  [MX_R0603_SMALL_T01]  167.11 153.86 270 bottom
PR5  100 Ohm  [MX_R0603_SMALL_T01]  168.38 153.86 270 bottom
PR8  0Ohm  [MX_R0402_SHORT_SMALL_T01]  159.08 161.13 0 top
PR9  200K  [MX_R0402_SMALL_T01]  162.66 153.28 270 top
PR10  75K  [MX_R0402_SMALL_T01]  162.33 151.93 0 top
PR11  1 OHM  [MX_R0402_SMALL_T01]  164.74 145.05 90 top
PR12  1 OHM  [MX_R0402_SMALL_T01]  162.71 145.05 90 top
PR25  2.2 Ohm  [MX_R0603_SMALL_T01]  45.52 134.66 90 top
PR26  845KOHM  [MX_R0402_SMALL_T01]  49.07 139.41 0 top
PR27  10K  [MX_R0402_SMALL_T01]  50.6 140.73 180 top
PR28  2.2  [MX_R0805_SMALL_T02]  54.76 136.74 0 bottom
PR29  10K  [MX_R0402_SMALL_T01]  52.22 140.73 180 top
PR30  0Ohm  [MX_R0805_SMALL_T02]  34.12 119.91 0 top
PR31  8.2KOHM  [MX_R0402_SMALL_T01]  35.05 117.98 90 top
PR32  39 Ohm  [MX_R0402_SMALL_T01]  81.43 104.79 0 top
PR33  4.7Ohm  [MX_R1206]  29.77 117.54 180 bottom
PR34  5.9KOHM  [MX_R0402_SMALL_T01]  53.29 134.46 270 top
PR35  100  [MX_R0402_SMALL_T01]  46.76 132.02 0 top
PR36  0Ohm  [MX_R0805_SMALL_T02]  32.66 112.36 0 top
PR37  0Ohm  [MX_R0402_SMALL_T01]  48.03 132.37 90 top
PR38  8.2KOHM  [MX_R0402_SMALL_T01]  32.59 114.83 0 top
PR39  4.02KOHM  [MX_R0402_SMALL_T01]  49.86 132.37 90 top
PR40  33 OHM  [MX_R0402_SMALL_T01]  74.04 104.92 180 top
PR41  510 Ohm  [MX_R0603_SMALL_T01]  47.39 137.94 180 top
PR42  15KOhm  [MX_R0402_SMALL_T01]  51.13 132.04 0 top
PR43  0Ohm  [MX_R0402_SHORT_SMALL_T01]  44.96 133.09 180 top
PR44  4.02KOHM  [MX_R0402_SMALL_T01]  46.94 133.97 180 top
PR45  100  [MX_R0402_SMALL_T01]  44.8 132.04 180 top
PR46  100 Ohm  [MX_R0402_SMALL_T01]  52.5 132.43 90 top
PR47  10KOhm  [MX_R0402_SMALL_T01]  46.76 132.96 180 top
PR49  0Ohm  [MX_R0805_SMALL_T02]  133.58 17.13 270 top
PR50  0Ohm  [MX_R0603_SHORT_SMALL_T01]  113.9 29.16 270 bottom
PR51  0  [MX_R0603_SMALL_T01]  102.35 28.95 0 bottom
PR52  1 Ohm  [MX_R0805_SMALL_T02]  114.92 31.18 180 bottom
PR53  2.2  [MX_R0805_SMALL_T02]  108.87 23.76 270 bottom
PR54  8.2KOHM  [MX_R0402_SMALL_T01]  133.06 14.93 90 top
PR55  0Ohm  [MX_R0805_SMALL_T02]  132.56 9.87 270 top
PR56  4.7Ohm  [MX_R1206]  124.1 11.75 270 bottom
PR57  8.2KOHM  [MX_R0402_SMALL_T01]  130.66 7.79 180 top
PR58  10KOhm  [MX_R0402_SMALL_T01]  107.45 33.09 270 bottom
PR59  1 Ohm  [MX_R0603_SMALL_T01]  114.41 27.43 0 bottom
PR60  88.7KOHM  [MX_R0402_SMALL_T01]  105.14 26.03 0 bottom
PR61  15.8K  [MX_R0402_SMALL_T01]  103.62 27.47 90 bottom
PR62  10.2KOHM  [MX_R0402_SMALL_T01]  102.35 27.89 180 bottom
PR63  93.1KOHM  [MX_R0402_SMALL_T01]  106.03 31.49 270 bottom
PR64  0  [MX_R0402_SMALL_T01]  105.01 24.63 90 bottom
PR65  2.2  [MX_R0805_SMALL_T02]  110.12 33.47 90 bottom
PR66  10K  [MX_R0402_SMALL_T01]  102.24 24.63 270 bottom
PR67  0Ohm  [MX_R0805_SMALL_T02]  88.92 32.02 180 bottom
PR68  8.2KOHM  [MX_R0402_SMALL_T01]  87.06 32.48 90 bottom
PR70  0Ohm  [MX_R0402_SHORT_SMALL_T01]  104.1 24.63 90 bottom
PR71  0Ohm  [MX_R0805_SMALL_T02]  88.95 34.25 180 bottom
PR72  4.7Ohm  [MX_R1206]  80.8 37.76 90 bottom
PR73  8.2KOHM  [MX_R0402_SMALL_T01]  87.07 34.99 90 bottom
PR74  10K  [MX_R0402_SMALL_T01]  106.16 34.39 0 bottom
PR75  6.81KOHM  [MX_R0402_SMALL_T01]  103.87 31.49 270 bottom
PR76  10KOhm  [MX_R0402_SMALL_T01]  102.6 30.98 180 bottom
PR95  0Ohm  [MX_R0805_SHORT_SMALL_T02]  80.01 66.89 270 top
PR96  10K  [MX_R0402_SMALL_T01]  72.49 64.25 90 bottom
PR97  2.2  [MX_R0805_SMALL_T02]  69.05 69.49 180 top
PR99  2.2  [MX_R0603_SMALL_T01]  69.45 65.91 90 top
PR101  4.7Ohm  [MX_R1206]  71.38 71.17 0 bottom
PR107  3.16KOhm  [MX_R0402_SMALL_T01]  75.58 65.53 270 top
PR108  0Ohm  [MX_R0402_SHORT_SMALL_T01]  77.02 65.53 0 bottom
PR109  10KOhm  [MX_R0402_SMALL_T01]  76.94 66.28 0 top
PR111  100KOHM  [MX_R0402_SMALL_T01]  67.8 100.99 90 bottom
PR112  0Ohm  [MX_R0402_SHORT_SMALL_T01]  70.97 90.72 180 bottom
PR113  100KOHM  [MX_R0402_SMALL_T01]  68.77 100.99 270 bottom
PR114  0Ohm  [MX_R0402_SHORT_SMALL_T01]  67.74 93.69 90 bottom
PR115  0  [MX_R0402_SMALL_T01]  68.68 93.69 90 bottom
PR116  10K  [MX_R0402_SMALL_T01]  101.15 43.56 0 bottom
PR117  2.2 Ohm  [MX_R0603_SMALL_T01]  101.96 37 180 bottom
PR118  0Ohm  [MX_R0402_SHORT_SMALL_T01]  103.86 42.92 180 bottom
PR119  21.5K  [MX_R0402_SMALL_T01]  90.89 41.4 90 bottom
PR120  10KOhm  [MX_R0402_SMALL_T01]  91.42 42.8 0 bottom
PR121  20KOhm  [MX_R0402_SMALL_T01]  28.6 23.84 270 bottom
PR122  22.6KOHM  [MX_R0402_SMALL_T01]  29.03 21.33 180 top
PR123  0  [MX_R0402_SMALL_T01]  69.62 93.69 90 bottom
PR124  2.2 Ohm  [MX_R0603_SMALL_T01]  142.93 30.71 180 bottom
PR125  2.2  [MX_R0805_SMALL_T02]  139.05 23.24 270 bottom
PR126  909KOhm  [MX_R0402_SMALL_T01]  139.05 32 270 bottom
PR127  0Ohm  [MX_R0805_SMALL_T02]  133.42 13.68 270 bottom
PR128  1K  [MX_R0402_SMALL_T01]  137.78 34.59 270 bottom
PR129  200  [MX_R0402_SMALL_T01]  136.51 34.59 270 bottom
PR130  8.2KOHM  [MX_R0402_SMALL_T01]  136.24 13.38 0 bottom
PR131  100K  [MX_R0402_SMALL_T01]  139.05 34.29 270 bottom
PR132  10K  [MX_R0402_SMALL_T01]  135.19 34.87 0 bottom
PR133  4.7Ohm  [MX_R1206]  140.41 15 90 bottom
PR134  0Ohm  [MX_R0805_SMALL_T02]  135.89 18.46 270 bottom
PR135  10KOhm  [MX_R0402_SMALL_T01]  140.32 34.29 270 bottom
PR136  8.2K  [MX_R0402_SMALL_T01]  135.99 18 0 top
PR139  20  [MX_R1206_H26]  147.43 23.26 180 bottom
PR141  20  [MX_R1206_H26]  147.43 27.91 180 bottom
PR214  7.87KOHM  [MX_R0402_SMALL_T01]  134.47 32.88 180 bottom
PR760  11KOHM  [MX_R0402_SMALL_T01]  28.37 106.67 90 bottom
PR761  20KOhm  [MX_R0402_SMALL_T01]  29.69 104.94 90 bottom
PR808  102KOhm  [MX_R0402_SMALL_T01]  76.4 67.66 90 top
PR1016  0Ohm  [MX_R0402_SHORT_SMALL_T01]  73.64 65.73 90 top
PR1017  10KOhm  [MX_R0402_SMALL_T01]  74.79 64.59 90 bottom
PR6301  0Ohm  [MX_R0402_SHORT_SMALL_T01]  44.8 143.2 270 bottom
PR6399  2.2 OHM  [MX_R0402_SMALL_T01]  157.69 165.05 270 top
PR6801  0Ohm  [MX_R0805_SHORT_SMALL_T02]  25.71 118.68 90 top
PR6802  0Ohm  [MX_R0402_SHORT_SMALL_T01]  53.41 132.43 270 top
PR7001  0Ohm  [MX_R0805_SHORT_SMALL_T02]  68.65 40.76 90 bottom
PR7002  0Ohm  [MX_R0805_SHORT_SMALL_T02]  64.87 47.64 0 bottom
PR7301  0Ohm  [MX_R0402_SHORT_SMALL_T01]  79.12 64.38 270 top
PR7401  0Ohm  [MX_R0805_SMALL_T02]  70.92 96.81 90 bottom
PR7601  12.7KOHM  [MX_R0402_SMALL_T01]  65.01 61.61 180 bottom
PR7602  10KOhm  [MX_R0402_SMALL_T01]  66.62 60.65 0 bottom
PR7607  0  [MX_R0402_SMALL_T01]  67.94 52.26 180 bottom
PR7608  2.2 Ohm  [MX_R0603_SMALL_T01]  59.82 51.35 0 bottom
PR7609  10K  [MX_R0402_SMALL_T01]  67.94 54.19 180 bottom
PR7701  0Ohm  [MX_R0402_SMALL_T01]  140.73 30.71 0 bottom
PR7702  0Ohm  [MX_R0402_SHORT_SMALL_T01]  141.67 32.18 180 bottom
PR8401  0Ohm  [MX_R0805_SHORT_SMALL_T02]  47.67 43.65 180 bottom
PR8402  0Ohm  [MX_R0805_SMALL_T02]  47.67 45.43 180 bottom
PR8403  0Ohm  [MX_R0805_SHORT_SMALL_T02]  49.5 41.9 225 bottom
PR8404  0Ohm  [MX_R0805_SHORT_SMALL_T02]  93.24 16.32 270 bottom
PR8405  0Ohm  [MX_R0805_SMALL_T02]  96.49 8.24 0 bottom
PR8406  0Ohm  [MX_R0805_SHORT_SMALL_T02]  52.2 41.8 270 bottom
PR8410  0Ohm  [MX_R0805_SHORT_SMALL_T02]  96.8 16.32 270 bottom
PR8901  2.2KOHM  [MX_R0402_SMALL_T01]  84.15 159.35 0 top
PR89001  100  [MX_R0402_SMALL_T01]  87.48 170.47 270 top
PR89002  45.3Ohm  [MX_R0402_SMALL_T01]  89.43 170.47 90 top
PR89004  10 OHM  [MX_R0402_SMALL_T01]  87.48 168.39 90 bottom
PR89005  1K  [MX_R0402_SMALL_T01]  94.33 169.41 180 top
PR89006  49.9  [MX_R0402_SMALL_T01]  89.43 168.39 90 bottom
PR89007  100K  [MX_R0402_SMALL_T01]  88.02 156.68 0 top
PR89008  10KOhm  [MX_R0402_SMALL_T01]  85.65 168.39 270 bottom
PR89009  0Ohm  [MX_R0402_SHORT_SMALL_T01]  89.05 167.71 0 top
PR89010  2.26KOHM  [MX_R0402_SMALL_T01]  84.91 159.63 0 bottom
PR89011  47  [MX_R0402_SMALL_T01]  86.33 166.87 180 bottom
PR89012  4.02K  [MX_R0402_SMALL_T01]  84.56 164.84 180 bottom
PR89013  100  [MX_R0402_SMALL_T01]  88.47 170.47 270 top
PR89014  0  [MX_R0402_SMALL_T01]  88.47 168.39 90 bottom
PR89015  2.2  [MX_R0805_SMALL_T02]  92.45 167.73 90 top
PR89016  2.26KOHM  [MX_R0402_SMALL_T01]  85.56 157.22 0 top
PR89017  100K  [MX_R0402_SMALL_T01]  86.33 159.12 270 bottom
PR89018  1K  [MX_R0402_SMALL_T01]  84.71 165.85 180 bottom
PR89019  560K  [MX_R0402_SMALL_T01]  86.76 164.53 270 bottom
PR89020  100  [MX_R0402_SMALL_T01]  83.01 166.18 0 top
PR89021  100K  [MX_R0402_SMALL_T01]  86.1 158.44 0 top
PR89022  2.26KOHM  [MX_R0402_SMALL_T01]  84.15 158.44 0 top
PR89023  0 Ohm  [MX_R0402_SMALL_T01]  84.5 165.95 270 top
PR89024  75KOhm  [MX_R0603_SMALL_T01]  82.98 163.95 180 top
PR89025  82.5KOHM  [MX_R0402_SMALL_T01]  85.72 164.02 270 top
PR89026  124KOHM  [MX_R0402_SMALL_T01]  84.58 163.82 270 top
PR89027  75KOhm  [MX_R0603_SMALL_T01]  82.98 161.51 180 top
PR89028  0  [MX_R0402_SMALL_T01]  84.17 168.42 0 top
PR89029  2.1KOHM  [MX_R0402_SMALL_T01]  85.95 168.19 0 top
PR89030  34KOHM  [MX_R0402_SMALL_T01]  83.01 165.04 0 top
PR89031  75KOhm  [MX_R0603_SMALL_T01]  82.98 162.73 180 top
PR89032  100  [MX_R0402_SMALL_T01]  84.17 167.5 0 top
PR89034  10  [MX_R0402_SMALL_T01]  84.3 162.42 180 bottom
PR89035  31.6KOHM  [MX_R0402_SMALL_T01]  89.89 166.74 180 top
PR89036  10K  [MX_R0402_SMALL_T01]  94.33 168.9 90 bottom
PR89037  10  [MX_R0402_SMALL_T01]  84.3 161.48 180 bottom
PR89038  15K  [MX_R0402_SMALL_T01]  92 157.24 270 top
PR89039  10  [MX_R0402_SMALL_T01]  85.57 161.91 270 bottom
PR89040  82.5KOHM  [MX_R0402_SMALL_T01]  88.11 156.96 90 bottom
PR89041  57.6KOHM  [MX_R0402_SMALL_T01]  91.16 156.96 270 bottom
PR89042  47  [MX_R0402_SMALL_T01]  98.14 166.61 0 top
PR89043  4.02K  [MX_R0402_SMALL_T01]  100.3 164.45 0 bottom
PR89044  1K  [MX_R0402_SMALL_T01]  96.75 165.6 270 top
PR89045  100K  [MX_R0402_SMALL_T01]  97 159.91 270 bottom
PR89046  560K  [MX_R0402_SMALL_T01]  98.07 164.81 0 bottom
PR89047  2.26KOHM  [MX_R0402_SMALL_T01]  99.21 160.09 180 bottom
PR89048  100  [MX_R0402_SMALL_T01]  100.81 167.12 270 top
PR89049  57.6KOHM  [MX_R0402_SMALL_T01]  90.14 156.96 270 bottom
PR89050  0 Ohm  [MX_R0402_SMALL_T01]  101.7 165.09 90 top
PR89051  0Ohm  [MX_R0402_SHORT_SMALL_T01]  99.21 161 0 bottom
PR89052  100K  [MX_R0402_SMALL_T01]  96.34 161.53 270 bottom
PR89053  0 Ohm  [MX_R0402_SMALL_T01]  98.88 167.76 180 bottom
PR89054  2.1KOHM  [MX_R0402_SMALL_T01]  97.23 167.86 180 bottom
PR89055  2.26KOHM  [MX_R0402_SMALL_T01]  98.17 162.85 180 bottom
PR89056  100  [MX_R0402_SMALL_T01]  100.3 170.17 180 top
PR89057  75KOhm  [MX_R0603_SMALL_T01]  97.84 162.6 0 top
PR89059  105KOhm  [MX_R0402_SMALL_T01]  93.88 163.64 180 top
PR89060  187KOhm  [MX_R0402_SMALL_T01]  92.3 162.35 270 top
PR89061  75KOhm  [MX_R0603_SMALL_T01]  97.84 163.85 0 top
PR89062  19.1KOHM  [MX_R0402_SMALL_T01]  95.15 163.59 90 top
PR89063  37.4KOhm  [MX_R0402_SMALL_T01]  94.56 165.47 90 top
PR89064  10KOhm  [MX_R0402_SMALL_T01]  93.06 160.39 270 top
PR89065  27.4kOHM  [MX_R0402_SMALL_T01]  92.18 156.96 90 bottom
PR89066  0  [MX_R0402_SMALL_T01]  96.75 167.25 270 top
PR89067  10  [MX_R0402_SMALL_T01]  95.48 160.64 270 top
PR89068  4.12KOHM  [MX_R0402_SMALL_T01]  87.86 154.93 180 bottom
PR89069  10  [MX_R0402_SMALL_T01]  99.01 161.1 0 top
PR89070  32.4K  [MX_R0402_SMALL_T01]  92.02 168.95 90 bottom
PR89071  8.2K  [MX_R0402_SMALL_T01]  121.82 144.47 90 top
PR89072  4.12KOHM  [MX_R0402_SMALL_T01]  140.19 144.31 270 top
PR89073  8.2K  [MX_R0402_SMALL_T01]  141.15 144.25 90 top
PR89105  2.2KOHM  [MX_R0402_SMALL_T01]  88.92 168.7 0 top
PR90001  0Ohm  [MX_R0805_SMALL_T02]  124.94 156.45 0 top
PR90002  2.2 Ohm  [MX_R0603_SMALL_T01]  113.08 149.88 0 bottom
PR90003  2.2  [MX_R0805_SMALL_T02]  116.61 145.61 0 bottom
PR90004  8.2KOHM  [MX_R0402_SMALL_T01]  127.35 154.5 180 top
PR90005  51 OHM  [MX_R0402_SMALL_T01]  114.5 148.3 0 bottom
PR90006  4.7Ohm  [MX_R1206]  126.72 147.69 0 bottom
PR90007  0Ohm  [MX_R0805_SMALL_T02]  129.67 148.68 90 top
PR90008  8.2KOHM  [MX_R0402_SMALL_T01]  129.25 150.87 90 top
PR90009  2.2 Ohm  [MX_R0603_SMALL_T01]  102.34 152.14 180 bottom
PR90010  2.2  [MX_R0805_SMALL_T02]  101.19 147.56 0 bottom
PR90011  0Ohm  [MX_R0805_SMALL_T02]  112.11 155.06 90 top
PR90012  8.2KOHM  [MX_R0402_SMALL_T01]  109.4 156.56 180 top
PR90013  51 OHM  [MX_R0402_SMALL_T01]  99.44 150.26 270 bottom
PR90014  4.7Ohm  [MX_R1206]  108.38 148 180 bottom
PR90015  0Ohm  [MX_R0805_SMALL_T02]  112.11 148.3 180 top
PR90016  8.2KOHM  [MX_R0402_SMALL_T01]  112.39 150 90 top
PR93001  0Ohm  [MX_R0805_SMALL_T02]  138.28 150.89 180 bottom
PR93002  2.2 Ohm  [MX_R0603_SMALL_T01]  160.95 122.28 270 bottom
PR93003  2.2  [MX_R0805_SMALL_T02]  163.6 126.05 0 top
PR93004  8.2KOHM  [MX_R0402_SMALL_T01]  138.78 149.14 270 bottom
PR93005  51 OHM  [MX_R0402_SMALL_T01]  161.75 126.02 270 top
PR93006  4.7Ohm  [MX_R1206]  135 148.68 180 bottom
PR93007  0Ohm  [MX_R0805_SMALL_T02]  167.23 124.86 90 top
PR93008  8.2KOHM  [MX_R0402_SMALL_T01]  137.77 143.47 180 top
PR93009  2.2 Ohm  [MX_R0603_SMALL_T01]  158.28 127.27 270 bottom
PR93010  2.2  [MX_R0805_SMALL_T02]  156.59 122.57 270 bottom
PR93011  0Ohm  [MX_R0805_SMALL_T02]  167.78 99.51 90 top
PR93012  8.2KOHM  [MX_R0402_SMALL_T01]  166.91 101.43 180 top
PR93013  51 OHM  [MX_R0402_SMALL_T01]  157.28 125.24 270 bottom
PR93014  4.7Ohm  [MX_R1206]  164.84 100.42 270 top
PR93015  0Ohm  [MX_R0805_SMALL_T02]  162.74 99.61 90 top
PR93016  8.2KOHM  [MX_R0402_SMALL_T01]  162.33 101.46 180 top
PR93024  10KOhm  [MX_R0402_SMALL_T01]  135.87 32.37 90 bottom
PR93026  316KOhm  [TX_R0402]  142.22 28.06 180 bottom
PR93028  20  [MX_R1206_H26]  147.43 25.63 180 bottom
PR93029  0Ohm  [MX_R0402_SHORT_SMALL_T01]  134.22 29.46 180 bottom
PR93038  1.21KOHM  [MX_R0402_SMALL_T01]  42.9 139.56 180 bottom
PR93039  200KOHM  [MX_R0402_SMALL_T01]  41.27 139.56 180 bottom
PR93046  2.26KOHM  [MX_R0402_SMALL_T01]  30.33 139.82 270 bottom
PR93051  2.26KOHM  [MX_R0402_SMALL_T01]  30.3 141.09 180 bottom
PR93052  6.81KOHM  [MX_R0402_SMALL_T01]  28.68 140.5 0 bottom
PR93054  10KOhm  [MX_R0402_SMALL_T01]  32.36 145.46 90 bottom
PR93055  750 OHM  [MX_R0402_SMALL_T01]  42.44 146.5 270 bottom
PR93060  10KOhm  [MX_R0402_SMALL_T01]  44.8 141.57 270 bottom
PR93061  10KOhm  [MX_R0402_SMALL_T01]  40.38 148.43 0 bottom
PR93062  30KOHM  [MX_R0402_SMALL_T01]  31.04 145.99 180 bottom
PR93063  10KOhm  [MX_R0402_SMALL_T01]  25.27 146.27 90 bottom
PR93064  0Ohm  [MX_R0402_SHORT_SMALL_T01]  113.64 61.13 180 bottom
PR93065  0Ohm  [MX_R0402_SHORT_SMALL_T01]  119.15 48.88 90 bottom
PR93066  4.7Ohm  [MX_R1206]  94.16 147.87 180 bottom
PR93067  0Ohm  [MX_R0805_SMALL_T02]  99.29 148.17 90 top
PR93068  2.2 Ohm  [MX_R0603_SMALL_T01]  90.7 139.59 180 top
PR93069  8.2KOHM  [MX_R0402_SMALL_T01]  96.95 156.96 180 bottom
PR93070  0Ohm  [MX_R0805_SMALL_T02]  99.13 156.38 180 bottom
PR93071  51 OHM  [MX_R0402_SMALL_T01]  87.65 139.49 0 top
PR93083  8.2KOHM  [MX_R0402_SMALL_T01]  60.15 74.92 90 bottom
PR93097  10KOhm  [MX_R0402_SMALL_T01]  71.66 65.73 90 top
PR93098  2.2  [MX_R0805_SMALL_T02]  85.8 142.36 90 top
PR93099  8.2KOHM  [MX_R0402_SMALL_T01]  99.76 150.6 90 top
PR93155  0Ohm  [MX_R0402_SHORT_SMALL_T01]  46.1 40.48 270 top
PR93156  0 Ohm  [MX_R0402_SMALL_T01]  34.01 24.37 90 top
PR93157  0Ohm  [MX_R0805_SHORT_SMALL_T02]  70.94 41.52 180 bottom
PR93158  0Ohm  [MX_R0805_SMALL_T02]  64.87 49.55 0 bottom
PR93160  0Ohm  [MX_R0805_SHORT_SMALL_T02]  98.6 16.32 270 bottom
PR93161  0Ohm  [MX_R0805_SHORT_SMALL_T02]  95.02 16.32 270 bottom
PR93162  3.74KOHM  [MX_R0402_SMALL_T01]  33.07 139.94 270 bottom
PR93163  2.8KOhm  [MX_R0402_SMALL_T01]  32.15 139.94 270 bottom
PR93164  2.32KOHM  [MX_R0402_SMALL_T01]  33.98 140.96 270 bottom
PR93165  2.21KOHM  [MX_R0402_SMALL_T01]  34.9 140.96 270 bottom
PR93166  10K  [MX_R0402_SMALL_T01]  69.25 54.51 270 bottom
PR93170  0Ohm  [MX_R0402_SHORT_SMALL_T01]  33.54 21.94 0 bottom
PRT89001  100K  [MX_R0402_SMALL_T01]  121.77 146.29 270 top
PRT89002  100K  [MX_R0402_SMALL_T01]  133.98 145.46 90 top
PRT89003  100K  [MX_R0402_SMALL_T01]  122.83 144.47 90 top
PRT89004  100K  [MX_R0402_SMALL_T01]  143 143.17 0 top
PT156  TPC26T  [MX_TPC26T_S4_68]  145.34 29.81 180 bottom
PT157  TPC26T  [MX_TPC26T_S4_68]  31.82 114.77 180 bottom
PT158  TPC26T  [MX_TPC26T_S4_68]  122.48 149.67 0 top
PT159  TPC26T  [MX_TPC26T_S4_68]  165.16 146.53 90 bottom
PT160  TPC26T  [MX_TPC26T_S4_68]  104.29 149.77 90 top
PT161  TPC26T  [MX_TPC26T_S4_68]  90.3 150.76 270 top
PT162  TPC26T  [MX_TPC26T_S4_68]  90.3 148.94 270 top
PT163  TPC26T  [MX_TPC26T_S4_68]  108.05 152.52 270 bottom
PT264  TPC26T  [MX_TPC26T_S4_68]  74.6 126.51 180 bottom
PU3  RT8204LGQW  [MX_QFN_16P_20_S118_P_2V]  50.77 135.93 270 top
PU4  RT6575BGQW  [MX_QFN_20P_16_S122_PD_4V]  108.44 28.95 90 bottom
PU5  AOZ2263QI-10  [TX_QFN_22P_20_S161_2PAD]  73.52 69.21 0 top
PU6  RT9025_25PSP  [MX_SOIC_8P_50_201X236PNIK4V]  96.38 40.64 270 bottom
PU7  AP2127K-ADJTRG1  [MX_SOT23_S5_2D4_H51]  32.14 24.41 270 bottom
PU9  RT8231BGQW  [MX_QFN_20P_16_S122_P_4V]  138.29 28.06 90 bottom
PU10  APL3523AQB-ITRG  [MX_DFN_14P_16_118X79_P_ANP]  68.02 45.58 90 bottom
PU30  INA199B1DCKR  [MX_SC70_S6_87X55]  155.95 165.27 0 top
PU76  AP2127K-ADJTRG1  [MX_SOT23_S5_2D4_H51]  32.26 103.29 180 bottom
PU7601  RT9025_25PSP  [MX_SOIC_8P_50_201X236PNIK4V]  64.24 56 180 bottom
PU8401  APL3523AQB-ITRG  [MX_DFN_14P_16_118X79_P_ANP]  41.79 43.38 270 bottom
PU8402  APL3523AQB-ITRG  [MX_DFN_14P_16_118X79_P_ANP]  96.68 11.01 270 bottom
PU89001  NCP81203  [MX_QFN_52P_16_S236_PD_4VIA]  91.79 162.8 0 bottom
PU90001  NCP81151MNTBG  [MX_DFN_8P_20_S79_PAD_ON]  117.24 149.01 90 bottom
PU90002  NCP81151MNTBG  [MX_DFN_8P_20_S79_PAD_ON]  101.47 149.79 90 bottom
PU93001  NCP81151MNTBG  [MX_DFN_8P_20_S79_PAD_ON]  162.91 123.84 270 top
PU93002  NCP81151MNTBG  [MX_DFN_8P_20_S79_PAD_ON]  158.88 121.78 0 bottom
PU93003  LM393  [MX_SO8_H69]  37.95 144.85 270 bottom
PU93004  NCP81151MNTBG  [MX_DFN_8P_20_S79_PAD_ON]  88.1 141.93 0 top
Q1  PMBS3906  [MX_SOT23]  24.48 66.03 0 bottom
Q2  NX7002AK  [TX_SOT23_2D4_T01_H43]  37.44 159.37 180 top
Q5  NX7002AK  [TX_SOT23_2D4_T01_H43]  82.54 78.99 0 top
Q6  NX7002AK  [TX_SOT23_2D4_T01_H43]  81.95 72.57 270 top
Q7  NX7002AK  [TX_SOT23_2D4_T01_H43]  78.95 78.96 180 top
Q8  NX7002AK  [TX_SOT23_2D4_T01_H43]  119.45 21.17 270 bottom
Q16  NX7002AK  [TX_SOT23_2D4_T01_H43]  2.63 28.73 180 top
Q17  NX7002AK  [TX_SOT23_2D4_T01_H43]  27.05 74.67 270 top
Q93  NX7002AK  [TX_SOT23_2D4_T01_H43]  58.22 47.16 270 bottom
